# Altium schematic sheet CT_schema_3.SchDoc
size 573 x 351 mm
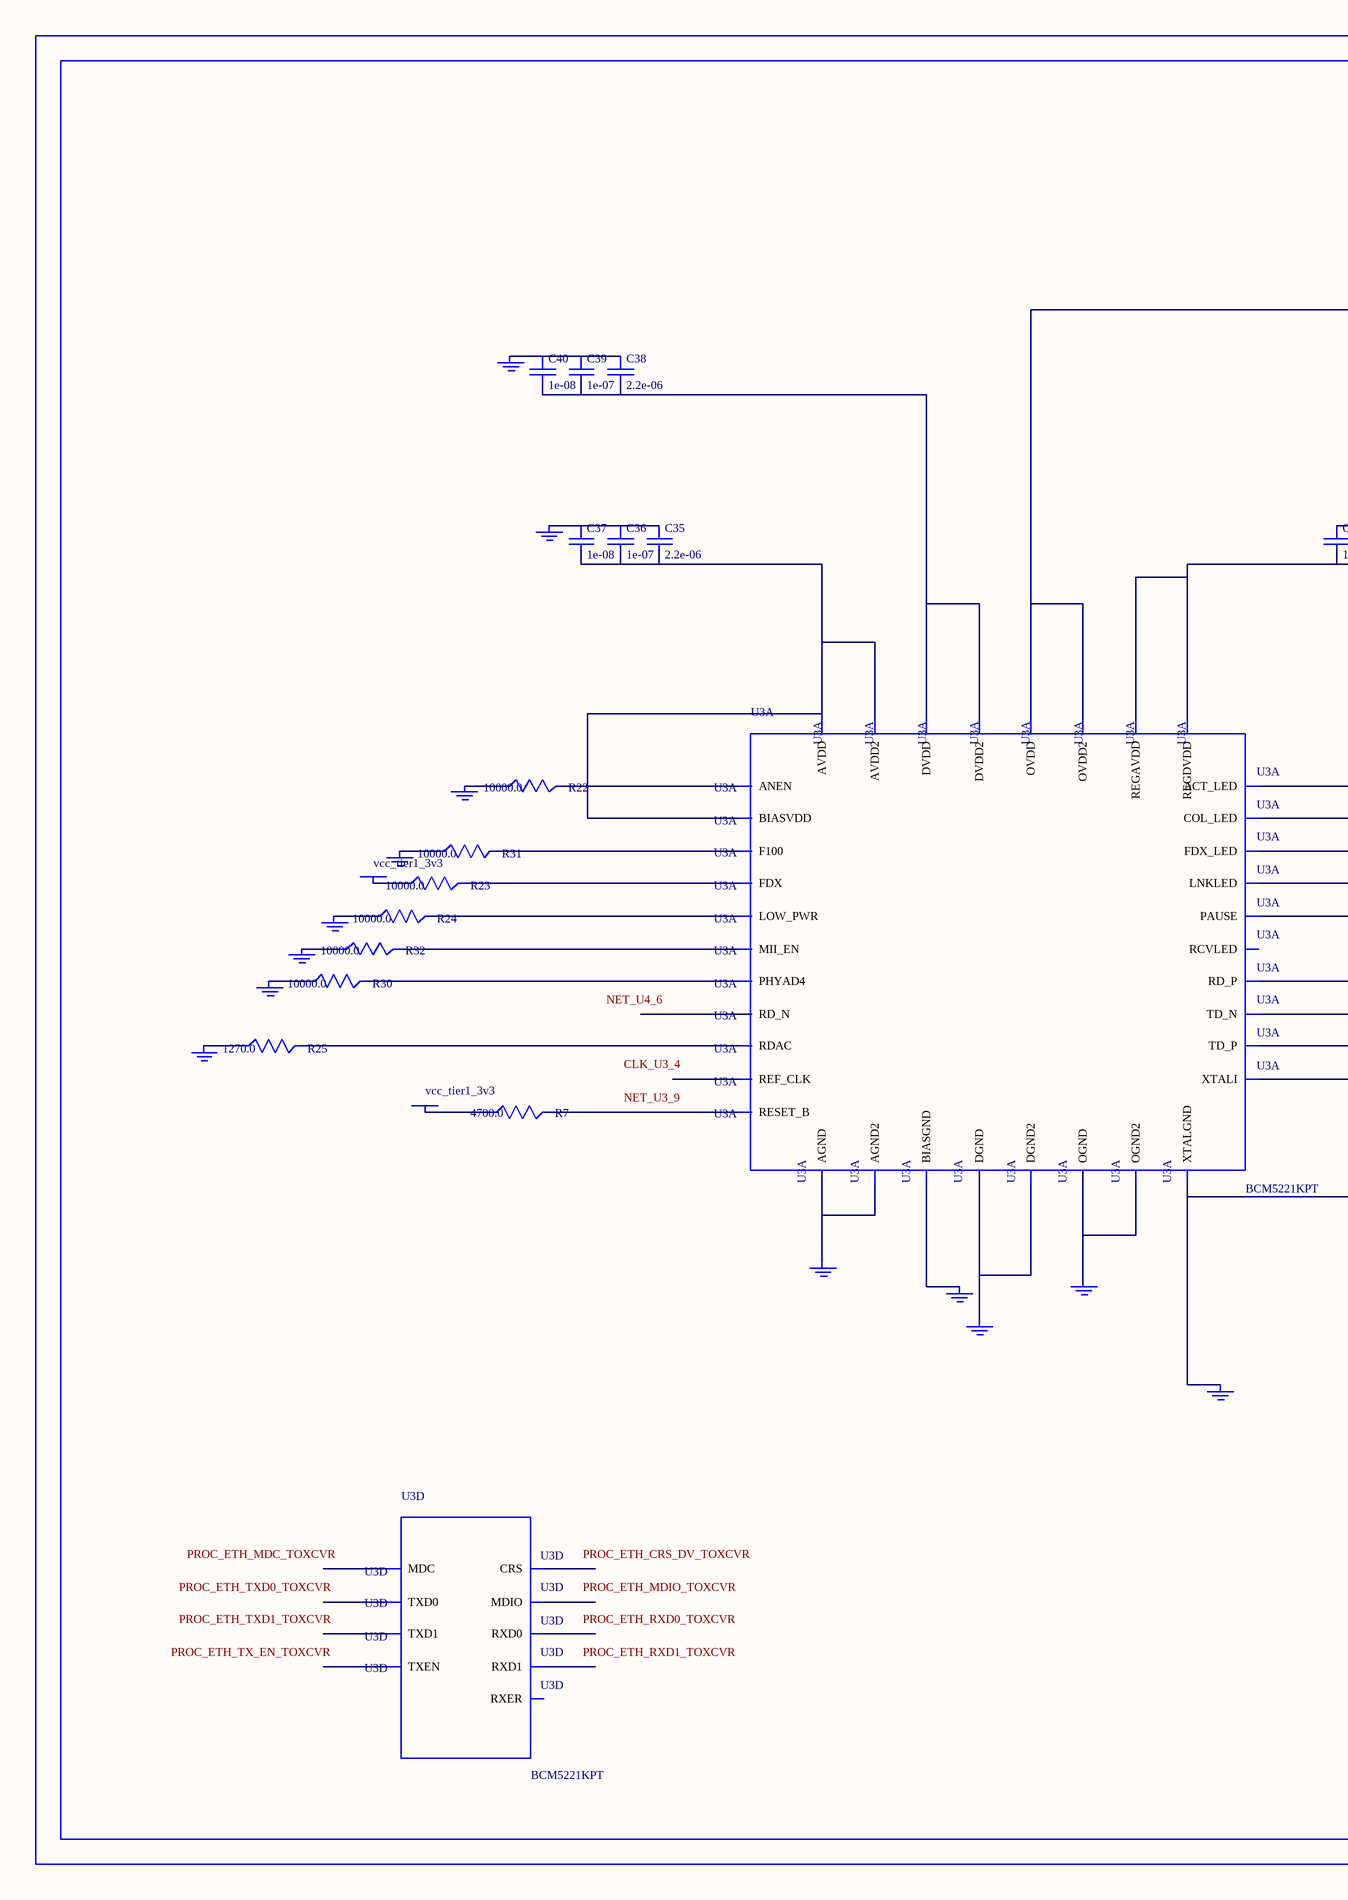
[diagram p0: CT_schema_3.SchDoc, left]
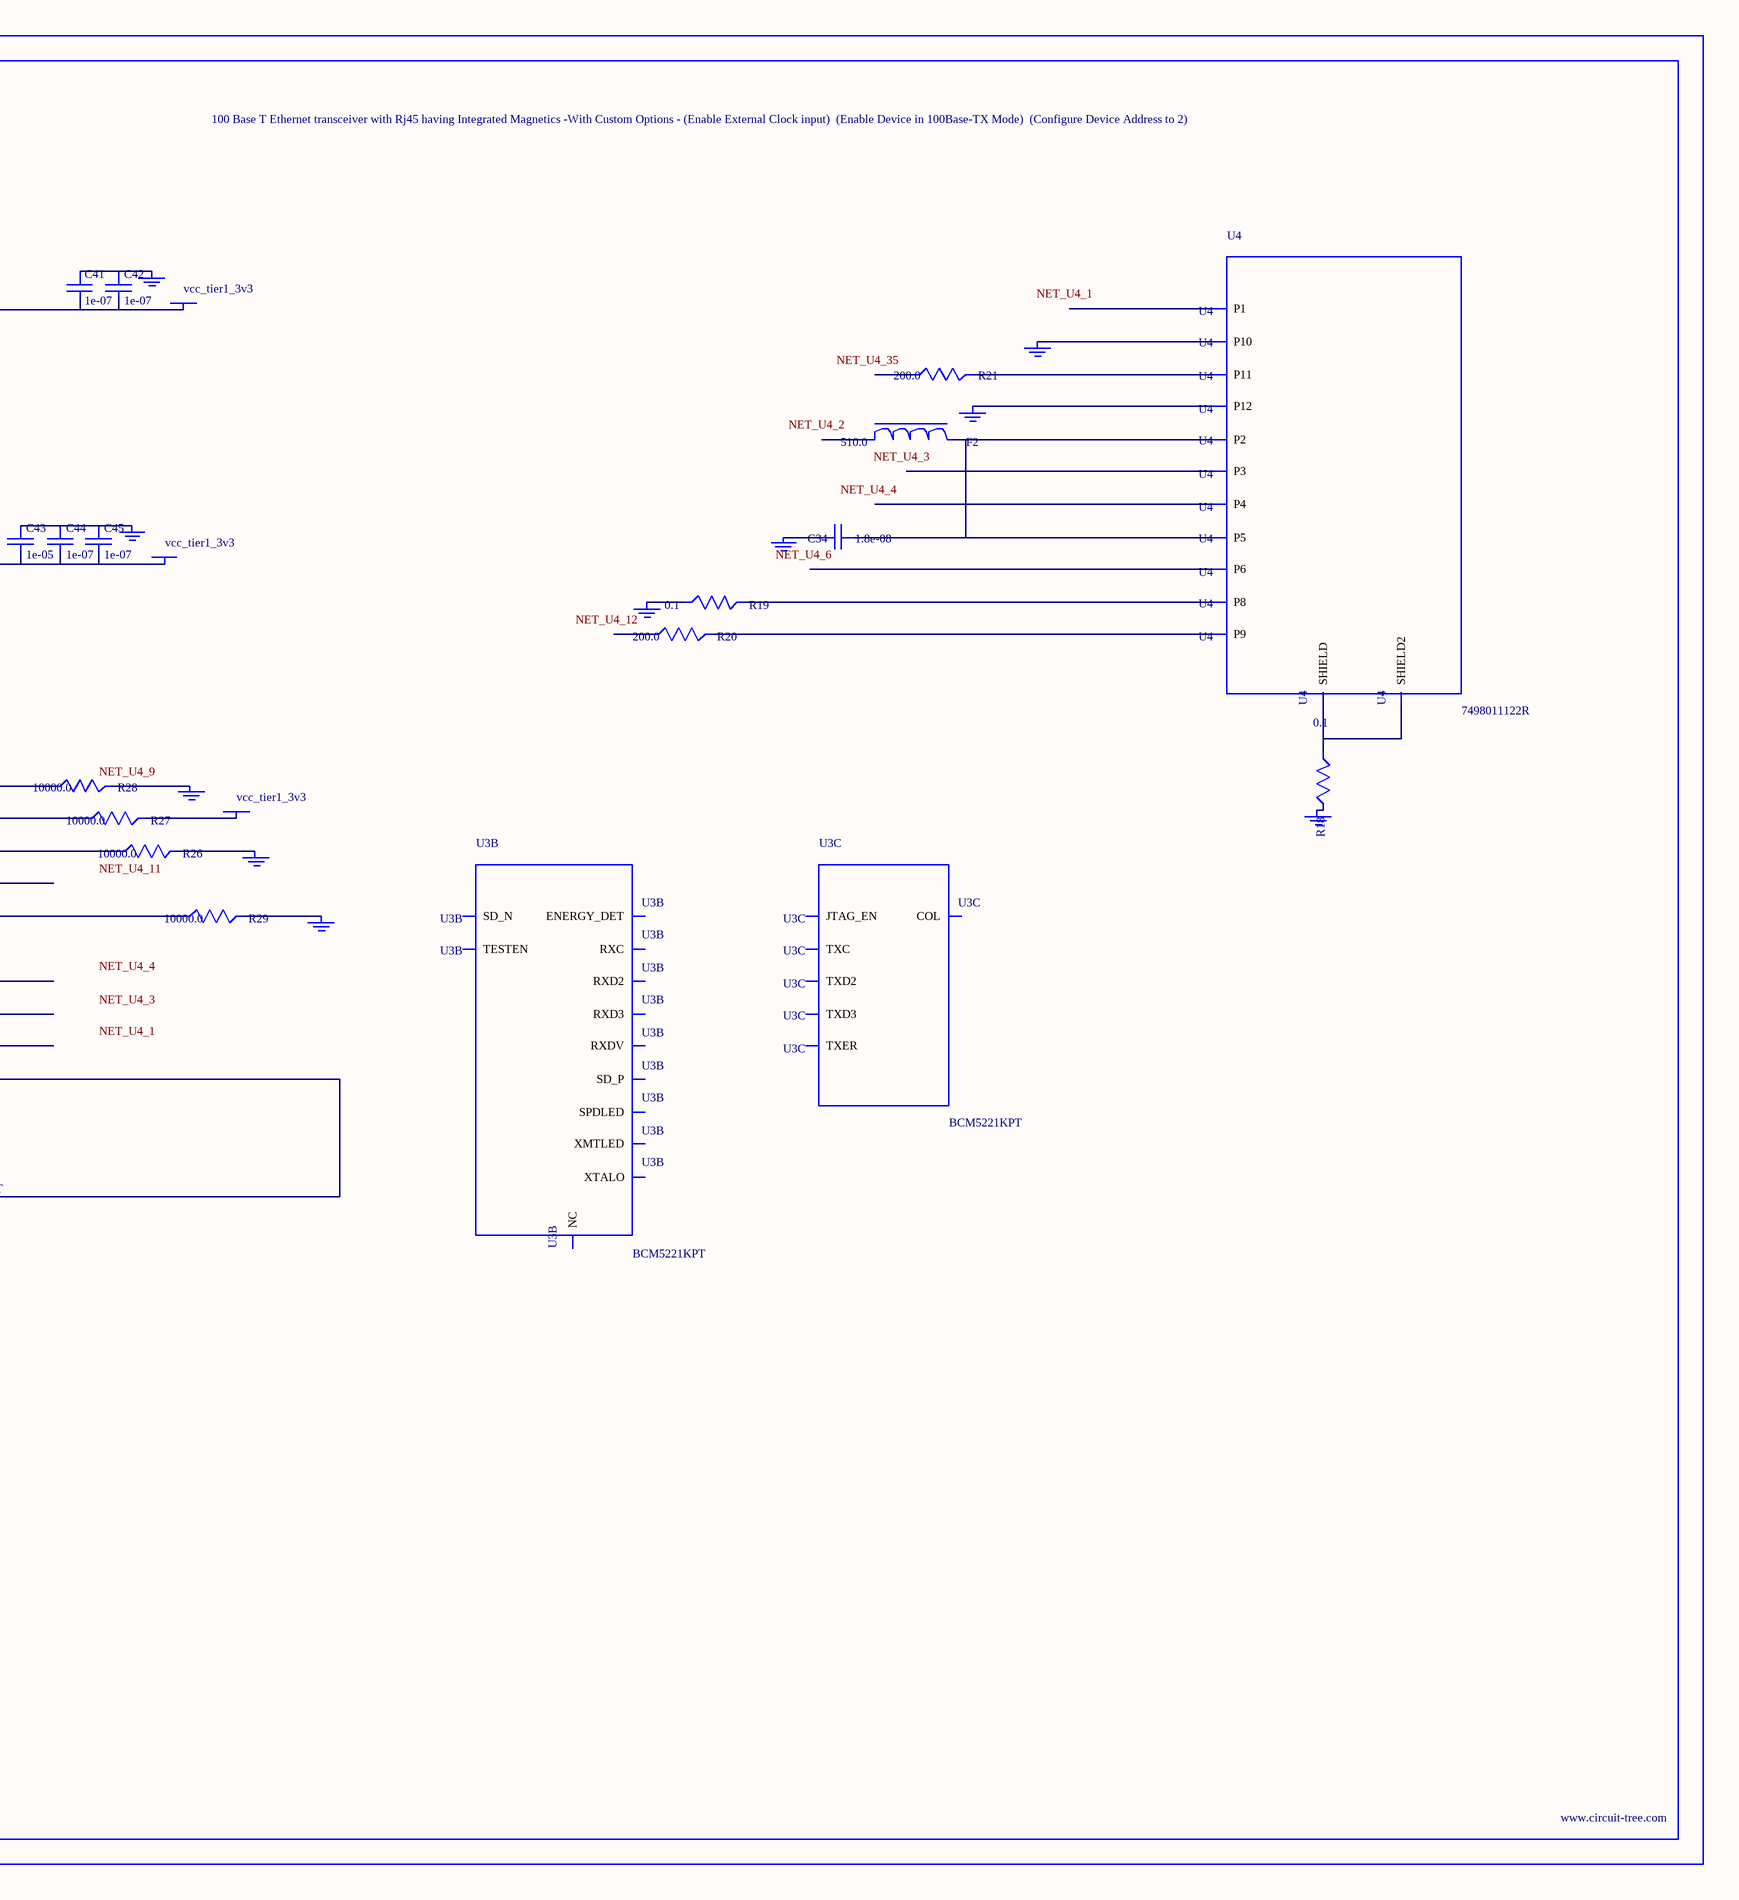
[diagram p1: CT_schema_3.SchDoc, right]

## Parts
BORDER2  (no value)
C34  1.8e-08  [C0402]
C35  2.2e-06  [C0603]
C36  1e-07  [C0402]
C37  1e-08  [C0402]
C38  2.2e-06  [C0603]
C39  1e-07  [C0402]
C40  1e-08  [C0402]
C41  1e-07  [C0402]
C42  1e-07  [C0402]
C43  1e-05  [C0805]
C44  1e-07  [C0402]
C45  1e-07  [C0402]
F2  510.0  [L0603]
GND_INSTANCE_2_0  (no value)
GND_INSTANCE_2_1  (no value)
GND_INSTANCE_2_2  (no value)
GND_INSTANCE_2_3  (no value)
GND_INSTANCE_2_4  (no value)
GND_INSTANCE_2_5  (no value)
GND_INSTANCE_2_6  (no value)
GND_INSTANCE_2_7  (no value)
GND_INSTANCE_2_8  (no value)
GND_INSTANCE_2_9  (no value)
GND_INSTANCE_2_10  (no value)
GND_INSTANCE_2_11  (no value)
GND_INSTANCE_2_12  (no value)
GND_INSTANCE_2_13  (no value)
GND_INSTANCE_2_14  (no value)
GND_INSTANCE_2_15  (no value)
GND_INSTANCE_2_16  (no value)
GND_INSTANCE_2_17  (no value)
GND_INSTANCE_2_18  (no value)
GND_INSTANCE_2_19  (no value)
GND_INSTANCE_2_20  (no value)
GND_INSTANCE_2_21  (no value)
GND_INSTANCE_2_22  (no value)
POWER_INSTANCE_2_0  vcc_tier1_3v3
POWER_INSTANCE_2_1  vcc_tier1_3v3
POWER_INSTANCE_2_2  vcc_tier1_3v3
POWER_INSTANCE_2_3  vcc_tier1_3v3
POWER_INSTANCE_2_4  vcc_tier1_3v3
R7  4700.0  [R0603]
R18  0.1  [R0603]
R19  0.1  [R0603]
R20  200.0  [R0603]
R21  200.0  [R0603]
R22  10000.0  [R0603]
R23  10000.0  [R0603]
R24  10000.0  [R0603]
R25  1270.0  [R0603]
R26  10000.0  [R0603]
R27  10000.0  [R0603]
R28  10000.0  [R0603]
R29  10000.0  [R0603]
R30  10000.0  [R0603]
R31  10000.0  [R0603]
R32  10000.0  [R0603]
U3  BCM5221KPT  [TQFP64_10X10MC]  (parts A,B,C,D of 4)
U4  7498011122R  [7498011122R]

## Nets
NetC34_1: C34.1 F2.2 U4.2(P2) U4.5(P5)
NetC34_2: C34.2 GND_INSTANCE_2_18.0(GND)
NetC35_1: C35.1 C36.1 C37.1 GND_INSTANCE_2_12.0(GND)
NetC35_2: C35.2 C36.2 C37.2 U3.22(BIASVDD) U3.27(AVDD) U3.28(AVDD2)
NetC38_1: C38.1 C39.1 C40.1 GND_INSTANCE_2_1.0(GND)
NetC38_2: C38.2 C39.2 C40.2 U3.2(DVDD) U3.55(DVDD2)
NetC41_1: C41.1 C42.1 GND_INSTANCE_2_0.0(GND)
NetC41_2: C41.2 C42.2 POWER_INSTANCE_2_0.0(PWR) U3.1(OVDD) U3.46(OVDD2)
NetC43_1: C43.1 C44.1 C45.1 GND_INSTANCE_2_2.0(GND)
NetC43_2: C43.2 C44.2 C45.2 POWER_INSTANCE_2_1.0(PWR) U3.3(REGDVDD) U3.20(REGAVDD)
NetGND_INSTANCE_2_3_0: GND_INSTANCE_2_3.0(GND) U3.6(XTALI) U3.7(XTALGND)
NetGND_INSTANCE_2_4_0: GND_INSTANCE_2_4.0(GND) R26.2
NetGND_INSTANCE_2_5_0: GND_INSTANCE_2_5.0(GND) R28.2
NetGND_INSTANCE_2_6_0: GND_INSTANCE_2_6.0(GND) R29.2
NetGND_INSTANCE_2_7_0: GND_INSTANCE_2_7.0(GND) R30.1
NetGND_INSTANCE_2_8_0: GND_INSTANCE_2_8.0(GND) R24.1
NetGND_INSTANCE_2_9_0: GND_INSTANCE_2_9.0(GND) R32.1
NetGND_INSTANCE_2_10_0: GND_INSTANCE_2_10.0(GND) R25.1
NetGND_INSTANCE_2_11_0: GND_INSTANCE_2_11.0(GND) U3.24(BIASGND)
NetGND_INSTANCE_2_13_0: GND_INSTANCE_2_13.0(GND) R31.1
NetGND_INSTANCE_2_14_0: GND_INSTANCE_2_14.0(GND) R22.1
NetGND_INSTANCE_2_15_0: GND_INSTANCE_2_15.0(GND) U3.29(AGND) U3.32(AGND2)
NetGND_INSTANCE_2_16_0: GND_INSTANCE_2_16.0(GND) U3.40(OGND) U3.45(OGND2)
NetGND_INSTANCE_2_17_0: GND_INSTANCE_2_17.0(GND) U3.54(DGND) U3.63(DGND2)
NetGND_INSTANCE_2_19_0: GND_INSTANCE_2_19.0(GND) R19.1
NetGND_INSTANCE_2_20_0: GND_INSTANCE_2_20.0(GND) U4.10(P10)
NetGND_INSTANCE_2_21_0: GND_INSTANCE_2_21.0(GND) U4.12(P12)
NetGND_INSTANCE_2_22_0: GND_INSTANCE_2_22.0(GND) R18.2
NetPOWER_INSTANCE_2_2_0: POWER_INSTANCE_2_2.0(PWR) R27.2
NetPOWER_INSTANCE_2_3_0: POWER_INSTANCE_2_3.0(PWR) R23.1
NetPOWER_INSTANCE_2_4_0: POWER_INSTANCE_2_4.0(PWR) R7.1
NetR7_2: R7.2 U3.9(RESET_B)
NetR18_1: R18.1 U4.13(SHIELD) U4.14(SHIELD2)
NetR19_2: R19.2 U4.8(P8)
NetR20_2: R20.2 U4.9(P9)
NetR21_2: R21.2 U4.11(P11)
NetR22_2: R22.2 U3.38(ANEN)
NetR23_2: R23.2 U3.39(FDX)
NetR24_2: R24.2 U3.16(LOW_PWR)
NetR25_2: R25.2 U3.23(RDAC)
NetR26_1: R26.1 U3.10(FDX_LED)
NetR27_1: R27.1 U3.11(COL_LED)
NetR28_1: R28.1 U3.12(ACT_LED)
NetR29_1: R29.1 U3.13(PAUSE)
NetR30_2: R30.2 U3.14(PHYAD4)
NetR31_2: R31.2 U3.37(F100)
NetR32_2: R32.2 U3.18(MII_EN)

Not connected (* = marked no-connect by the designer): F2 1; R20 1; R21 1; U3 4(REF_CLK) 5(XTALO) 8(NC) 15(TESTEN) 17(ENERGY_DET) 19(SD_N) 21(SD_P) 25(RD_N) 26(RD_P) 30(TD_N) 31(TD_P) 33(RCVLED) 34(XMTLED) 35(LNKLED) 36(SPDLED) 41(MDIO) 42(MDC) 43(RXD3) 44(RXD2) 47(RXD1) 48(RXD0) 49(RXDV) 50(RXC) 51(RXER) 52(TXER) 53(TXC) 56(TXEN) 57(TXD0) 58(TXD1) 59(TXD2) 60(TXD3) 61(COL) 62(CRS) 64(JTAG_EN); U4 1(P1) 3(P3) 4(P4) 6(P6)

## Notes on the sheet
- Labels drawn without touching a wire or pin: CLK_U3_4, NET_U3_9, NET_U4_1, NET_U4_2, NET_U4_3, NET_U4_4, NET_U4_6, NET_U4_9, NET_U4_11, NET_U4_12, NET_U4_35, PROC_ETH_CRS_DV_TOXCVR, PROC_ETH_MDC_TOXCVR, PROC_ETH_MDIO_TOXCVR, PROC_ETH_RXD0_TOXCVR, PROC_ETH_RXD1_TOXCVR, PROC_ETH_TX_EN_TOXCVR, PROC_ETH_TXD0_TOXCVR, PROC_ETH_TXD1_TOXCVR

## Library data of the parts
BORDER2 = BORDER_PAGE2
C34 = C0402C183K3RAC
C35 C38 = C0603C225K8RACTU
C36 C39 C41 C42 C44 C45 = C0402C104K3RACTU
C37 C40 = C0402C103K3RAC
C43 = C0805C106K8RACTU
F2 = ERA3APB511V
GND_INSTANCE_2_0-GND_INSTANCE_2_22 = GND
POWER_INSTANCE_2_0-POWER_INSTANCE_2_4 = PWR
R7 = RC0603JR-074K7L
R18 R19 = ERJ-3RSFR10V
R20 R21 = RC0603JR-07200RL
R22-R24 R26-R32 = RC0603JR-0710KL
R25 = RC0603FR-071K27L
